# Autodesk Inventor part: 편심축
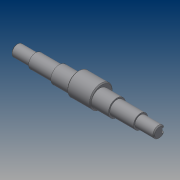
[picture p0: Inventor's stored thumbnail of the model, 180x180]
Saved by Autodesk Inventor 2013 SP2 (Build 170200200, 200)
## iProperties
Created: 2014-12
Part Number: 편심축
Material: Generic
Document SubType Name: Modeling
Designer: CADB303
Density: 1 g/cm^3
Author: CADB303
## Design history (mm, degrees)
sketch "스케치1"
  geometry: L1 (-75.5, 0)-(75.5, 0); L2 (-75.5, 0)-(-75.5, 6); L3 (-75.5, 6)-(-55.5, 6); L4 (-55.5, 6)-(-55.5, 7.5); L5 (-55.5, 7.5)-(-30.5, 7.5); L6 (-30.5, 7.5)-(-30.5, 9); L7 (-30.5, 9)-(-12.5, 9); L8 (-12.5, 2)-(-12.5, 14); L9 (-12.5, 14)-(12.5, 14); L10 (12.5, 14)-(12.5, 2); L11 (12.5, 9)-(30.5, 9); L12 (30.5, 9)-(30.5, 7.5); L13 (30.5, 7.5)-(55.5, 7.5); L14 (55.5, 7.5)-(55.5, 6); L15 (75.5, 6)-(75.5, 0); L16 (55.5, 6)-(75.5, 6); L17 (-12.5, 2)-(12.5, 2); 2 further points
  constraints: 34 end point, 11 parallel, 5 perpendicular, 2 point on line, 1 coincident, 1 horizontal, 1 midpoint
  dimensions: "d0" = 151 distance of L1.start L1.end; "d2" = 12 diameter of L3 L1; "d3" = 15 diameter of L5 L1; "d4" = 18 diameter of L7 L1; "d6" = 18 diameter of L11 L1; "d7" = 15 diameter of L13 L1; "d8" = 12 diameter of L16 L1; "d9" = 20 distance between parallel lines of L4 L2; "d10" = 25 distance between parallel lines of L6 L4; "d11" = 18 distance between parallel lines of L8 L6; "d12" = 20 distance between parallel lines of L14 L15; "d13" = 25 distance between parallel lines of L12 L14; "d14" = 18 distance between parallel lines of L10 L12; "d15" = 4 diameter of L17 L1; "d17" = 24 diameter of L9 L17
revolve "회전2" stored, may be unused: angle "d18" = 90 deg
revolve "회전3" stored, may be unused: angle "d19" = 90 deg
node "작업 평면1"
sketch "스케치2"
  geometry: L1 (10, 6)-(10, -6) reference; L2 (10, 2.5)-(-4, 2.5); L3 (-4, 2.5)-(-4, -2.5); L4 (-4, -2.5)-(10, -2.5); L5 (-141, 6)-(-141, -6) reference; 3 further points
  constraints: 6 end point, 2 midpoint, 2 point on line, 1 horizontal, 1 horizontal alignment, 1 parallel, 1 perpendicular
  dimensions: "d20" = 5 distance of L2.end L3.end; "d22" = 14 distance of L2.start L2.end
extrude "돌출1" cut sketch "스케치2" distance "d23" = 3; taper "d24" = 0 deg
fillet "모깎기1" dims "d25" = 2.5
chamfer "모따기1" distance "d26" = 1; stored, may be unused: second distance "d27" = 2, angle "d28" = 45 deg
node "솔리드2"
mirror "대칭1"
